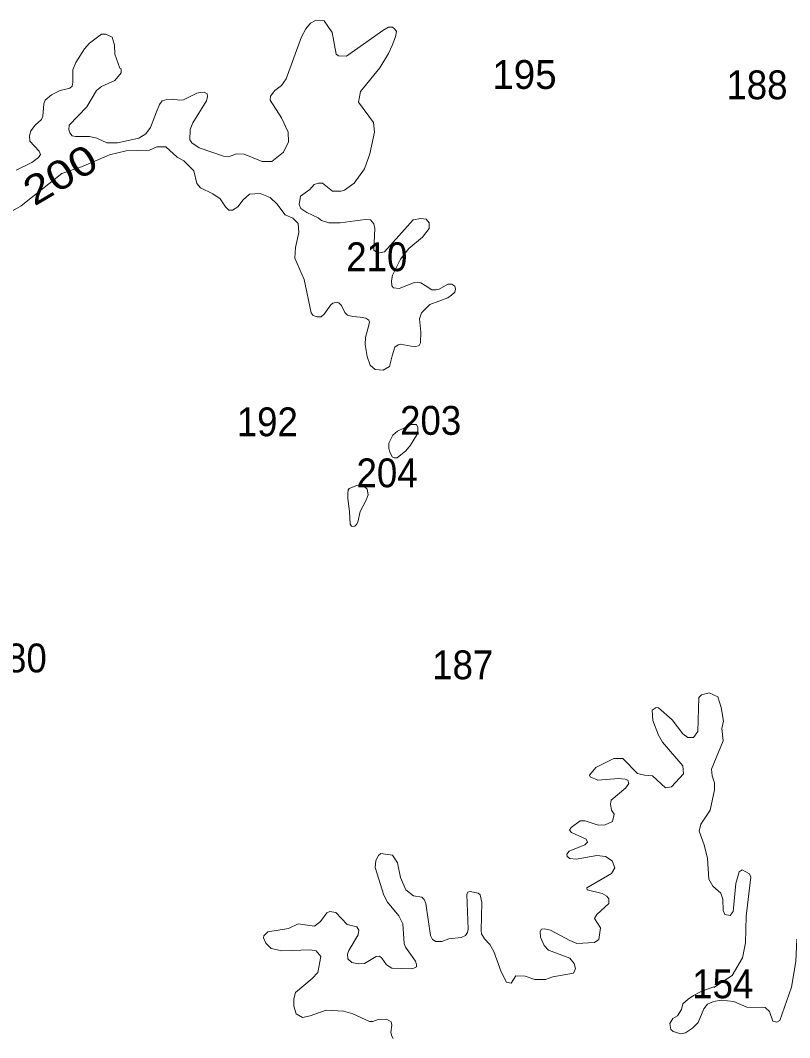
# Model space of a CAD drawing. Extents: x 499.9 to 555.3, y 9281.5 to 9336.8.
# Drawn here: x 524.08 to 528.35, y 9331.07 to 9336.71 of the extents above; entities that cross this region are included whole.
import ezdxf
from ezdxf.enums import TextEntityAlignment as Align

# ---------------------------------------------------------------- set-up
doc = ezdxf.new("R2010")
doc.units = 0
doc.header["$LTSCALE"] = 0.064
doc.layers.add('2', color=7, linetype='Continuous', lineweight=13)
doc.layers.add('21', color=7, linetype='Continuous')
doc.layers.add('61', color=7, linetype='Continuous')

msp = doc.modelspace()

# ---------------------------------------------------------------- linework, layer by layer
at = {"layer": '2'}
for points in [[(526.3906, 9335.2186), (526.3669, 9335.2186), (526.3294, 9335.2442), (526.3049, 9335.2586), (526.2873, 9335.2624), (526.27, 9335.2592), (526.1864, 9335.2264), (526.1547, 9335.2296), (526.1451, 9335.241), (526.1438, 9335.2693), (526.1491, 9335.3005), (526.1933, 9335.3903), (526.24, 9335.4481), (526.3154, 9335.5111), (526.3523, 9335.5599), (526.3525, 9335.5912), (526.3349, 9335.6121), (526.3054, 9335.6147), (526.2634, 9335.6082), (526.1047, 9335.4307), (526.068, 9335.4223), (526.0453, 9335.439), (526.0514, 9335.559), (526.0449, 9335.5863), (526.0275, 9335.608), (525.9979, 9335.6095), (525.8583, 9335.5908), (525.7946, 9335.5911), (525.7551, 9335.6033), (525.7364, 9335.6195), (525.673, 9335.649), (525.6407, 9335.6709), (525.6302, 9335.6928), (525.6387, 9335.7383), (525.6898, 9335.7753), (525.7133, 9335.8042), (525.7387, 9335.812), (525.7602, 9335.8102), (525.8153, 9335.7661), (525.8614, 9335.766), (525.883, 9335.7719), (525.9354, 9335.8106), (525.993, 9335.8909), (526.0234, 9335.9746), (526.0483, 9336.0946), (526.0432, 9336.1486), (525.9606, 9336.2609), (525.9714, 9336.3194), (526.0775, 9336.451), (526.1263, 9336.5299), (526.1466, 9336.5745), (526.1644, 9336.6222), (526.1703, 9336.6522), (526.1622, 9336.6661), (526.1487, 9336.6764), (526.1257, 9336.6774), (526.0944, 9336.659), (525.8926, 9336.5166), (525.8495, 9336.5174), (525.8368, 9336.5274), (525.8148, 9336.6463), (525.7704, 9336.7118), (525.7212, 9336.7145), (525.6945, 9336.6993), (525.6673, 9336.6671), (525.6442, 9336.6229), (525.5581, 9336.3899), (525.5331, 9336.3524), (525.4967, 9336.325), (525.4719, 9336.2934), (525.4693, 9336.2721), (525.5327, 9336.1734), (525.5692, 9336.0945), (525.5722, 9336.0406), (525.5438, 9335.9826), (525.4801, 9335.9317), (525.4262, 9335.9316), (525.3257, 9335.9714), (525.2831, 9335.9739), (525.2398, 9335.9572), (525.2104, 9335.9601), (525.0767, 9336.0076), (525.0356, 9336.0341), (525.0251, 9336.0522), (525.0257, 9336.1082), (525.0403, 9336.1463), (525.1169, 9336.2684), (525.1231, 9336.2927), (525.1206, 9336.3073), (525.1038, 9336.3154), (525.0813, 9336.3146), (525.0626, 9336.3099), (524.9886, 9336.274), (524.9685, 9336.2723), (524.9287, 9336.2767)], [(524.8065, 9336.1198), (524.7808, 9336.0855), (524.7424, 9336.0609), (524.6239, 9336.035), (524.5634, 9336.035), (524.5093, 9336.0603), (524.4682, 9336.0692), (524.3909, 9336.0693), (524.3721, 9336.0738), (524.3582, 9336.0899), (524.3528, 9336.1066), (524.3556, 9336.133), (524.4536, 9336.2339), (524.5075, 9336.3251), (524.5344, 9336.3474), (524.6079, 9336.3805), (524.6429, 9336.4224), (524.6428, 9336.4446), (524.636, 9336.4492), (524.6078, 9336.5273), (524.6062, 9336.5776), (524.5928, 9336.6203), (524.5578, 9336.6377), (524.5343, 9336.6376), (524.4674, 9336.5878), (524.4405, 9336.5563), (524.3925, 9336.4806), (524.3759, 9336.4408), (524.3763, 9336.3717), (524.3713, 9336.3491), (524.3591, 9336.339), (524.3058, 9336.3261), (524.2579, 9336.302), (524.2227, 9336.2712), (524.215, 9336.2517), (524.2093, 9336.1828), (524.2023, 9336.1647), (524.1672, 9336.1336), (524.1422, 9336.1013), (524.1347, 9336.0734), (524.1372, 9336.0447), (524.1887, 9335.9893), (524.1953, 9335.9696), (524.1842, 9335.9542), (524.1476, 9335.9257), (524.0605, 9335.8838)], [(524.9287, 9336.2767), (524.8968, 9336.2754), (524.8714, 9336.2673), (524.8566, 9336.2467), (524.8396, 9336.2069), (524.8065, 9336.1198)], [(524.0027, 9335.6357), (524.0886, 9335.6862), (524.3153, 9335.8639), (524.4235, 9335.9015), (524.5789, 9335.9688), (524.6717, 9335.9903), (524.8004, 9335.9934), (524.8421, 9336.0124), (524.8912, 9336.0123), (524.9541, 9335.955), (524.9906, 9335.9341), (525.0471, 9335.8788), (525.0638, 9335.81), (525.0835, 9335.7857), (525.1516, 9335.752), (525.193, 9335.7234), (525.2217, 9335.6795), (525.241, 9335.6616), (525.2612, 9335.6615), (525.2909, 9335.6806), (525.3195, 9335.7182), (525.3546, 9335.7497), (525.4149, 9335.7531), (525.4706, 9335.7308), (525.5072, 9335.6959), (525.5536, 9335.6356), (525.5953, 9335.6173), (525.6252, 9335.5874), (525.6297, 9335.5368), (525.6107, 9335.4533), (525.6076, 9335.395), (525.6578, 9335.2772), (525.6969, 9335.0915), (525.7086, 9335.076), (525.7313, 9335.0698), (525.7539, 9335.0692), (525.7703, 9335.0844), (525.8068, 9335.1361), (525.818, 9335.146), (525.84, 9335.151), (525.8514, 9335.1473), (525.8652, 9335.1324), (525.8841, 9335.0938), (525.8995, 9335.0784), (525.9287, 9335.0705), (525.9689, 9335.0684), (526.001, 9335.0617), (526.0173, 9335.0515), (526.0205, 9335.0404), (526.0179, 9335.0236), (525.9991, 9334.9542), (525.9962, 9334.9168), (526.0085, 9334.85), (526.0246, 9334.8013), (526.0517, 9334.7774), (526.0961, 9334.7731), (526.1318, 9334.7941), (526.1461, 9334.8532), (526.161, 9334.9003), (526.1799, 9334.9149), (526.1913, 9334.9172), (526.2733, 9334.9022), (526.2973, 9334.9113), (526.3039, 9334.9246), (526.3065, 9334.9843), (526.2984, 9335.0585), (526.3096, 9335.0912), (526.3566, 9335.1383), (526.4564, 9335.1744), (526.476, 9335.1895), (526.4936, 9335.2064), (526.4984, 9335.2221)], [(526.4984, 9335.2221), (526.4937, 9335.2403), (526.4779, 9335.2505), (526.4549, 9335.2499), (526.4074, 9335.2222), (526.3906, 9335.2186)], [(527.2166, 9332.2738), (527.29, 9332.2487), (527.328, 9332.2508), (527.3698, 9332.2687), (527.3773, 9332.3092), (527.3641, 9332.3314), (527.3584, 9332.3657), (527.3615, 9332.3877), (527.4422, 9332.4555), (527.4597, 9332.481), (527.4535, 9332.4982), (527.4392, 9332.505), (527.4021, 9332.5079), (527.2867, 9332.4989), (527.2445, 9332.5173), (527.2409, 9332.5272), (527.2756, 9332.5685), (527.3755, 9332.6194), (527.4265, 9332.6194), (527.5081, 9332.5354), (527.5462, 9332.5256), (527.5911, 9332.5234), (527.6633, 9332.4563), (527.6962, 9332.4625), (527.7629, 9332.5331), (527.7593, 9332.5788), (527.6464, 9332.7102), (527.6244, 9332.7477), (527.5923, 9332.8306), (527.5882, 9332.8877), (527.6107, 9332.9018), (527.6239, 9332.9), (527.7004, 9332.8343), (527.7592, 9332.7554), (527.7875, 9332.7362), (527.8174, 9332.7359), (527.8421, 9332.7689), (527.8475, 9332.9579), (527.8625, 9332.9721), (527.905, 9332.9836), (527.9528, 9332.9603), (527.9723, 9332.9019), (527.9851, 9332.8255), (527.9759, 9332.7858), (527.982, 9332.7165), (527.9187, 9332.5605), (527.9216, 9332.5231), (527.9344, 9332.4833), (527.9343, 9332.4452), (527.9104, 9332.3315), (527.8582, 9332.255), (527.8488, 9332.2161), (527.8773, 9332.1397), (527.8962, 9332.064), (527.903, 9331.9488), (527.925, 9331.9097), (527.9695, 9331.8722), (527.9803, 9331.838), (527.9832, 9331.7754), (527.9921, 9331.7524), (528.0218, 9331.7474), (528.0374, 9331.7706), (528.0539, 9331.9247), (528.0717, 9331.9895), (528.0879, 9332.0014), (528.1289, 9331.9784), (528.1364, 9331.9597), (528.1098, 9331.7445), (528.1067, 9331.5967), (528.0897, 9331.5124), (528.0319, 9331.4148), (527.9317, 9331.3488)], [(527.2232, 9332.1712), (527.1412, 9332.2091), (527.1298, 9332.2221), (527.14, 9332.2369), (527.1903, 9332.2739), (527.2166, 9332.2738)], [(525.9602, 9331.48), (525.9942, 9331.4817), (526.0573, 9331.5207), (526.0762, 9331.5212), (526.0893, 9331.511), (526.1154, 9331.4737), (526.1456, 9331.4547), (526.2524, 9331.4527), (526.2677, 9331.4551), (526.2814, 9331.4623), (526.2813, 9331.4768), (526.2766, 9331.4938), (526.2213, 9331.5723), (526.2126, 9331.5931), (526.2057, 9331.7024), (526.1836, 9331.7457), (526.1203, 9331.8226), (526.1008, 9331.8604), (526.0521, 9332.015), (526.0563, 9332.0537), (526.0709, 9332.0813), (526.0842, 9332.0925), (526.1489, 9332.0824), (526.1762, 9332.04), (526.1934, 9331.959), (526.222, 9331.891), (526.2655, 9331.8561), (526.3106, 9331.8487), (526.3234, 9331.8368), (526.3339, 9331.8145), (526.3588, 9331.6373), (526.3702, 9331.615), (526.3893, 9331.6034), (526.4224, 9331.6042), (526.4607, 9331.6182), (526.529, 9331.626), (526.5544, 9331.637), (526.5648, 9331.653), (526.5691, 9331.6727), (526.5609, 9331.8643), (526.5658, 9331.8767), (526.5801, 9331.8808), (526.6236, 9331.8714), (526.6353, 9331.8618), (526.6435, 9331.8203), (526.6396, 9331.6644), (526.6424, 9331.6452), (526.6593, 9331.6191), (526.6877, 9331.5871), (526.7105, 9331.5483), (526.751, 9331.4352), (526.7808, 9331.3783), (526.8077, 9331.3726), (526.8335, 9331.413), (526.884, 9331.4113), (526.9382, 9331.3925), (526.9969, 9331.3924), (527.0385, 9331.407), (527.1526, 9331.4276), (527.1638, 9331.4529), (527.1572, 9331.4808), (527.1314, 9331.5119), (527.0146, 9331.5563), (526.9896, 9331.5812), (526.9705, 9331.6281), (526.9672, 9331.6587), (526.9755, 9331.6721), (526.9919, 9331.6744), (527.0253, 9331.6671), (527.1321, 9331.6082), (527.1712, 9331.5929), (527.2691, 9331.5979), (527.2931, 9331.6142), (527.3026, 9331.679), (527.2698, 9331.7304), (527.282, 9331.7535), (527.3481, 9331.814), (527.3486, 9331.8403), (527.3373, 9331.8554), (527.3119, 9331.8706), (527.2281, 9331.8901), (527.2275, 9331.9012), (527.363, 9331.9807), (527.3822, 9332.0125), (527.3677, 9332.051), (527.3305, 9332.076), (527.2819, 9332.0814), (527.1681, 9332.061), (527.133, 9332.064), (527.1167, 9332.0753), (527.1151, 9332.0878), (527.1281, 9332.1039), (527.2158, 9332.1401), (527.2304, 9332.1554), (527.2232, 9332.1712)], [(526.1532, 9331.0645), (526.1445, 9331.0775), (526.1399, 9331.0977), (526.1455, 9331.1386), (526.1415, 9331.157), (526.1149, 9331.1726), (526.0699, 9331.1711), (526.0404, 9331.1601), (526.0213, 9331.1602), (525.9292, 9331.2016), (525.8763, 9331.2173), (525.7812, 9331.2218), (525.6925, 9331.1905), (525.6496, 9331.1818), (525.6143, 9331.203), (525.6007, 9331.2438), (525.6008, 9331.2851), (525.6108, 9331.321), (525.7035, 9331.3982), (525.7346, 9331.4324), (525.7518, 9331.5202), (525.7258, 9331.551), (525.6923, 9331.557), (525.5344, 9331.5516), (525.4753, 9331.5653), (525.4465, 9331.5936), (525.433, 9331.6234), (525.4347, 9331.6348), (525.4568, 9331.6569), (525.5718, 9331.6756), (525.625, 9331.7011), (525.7156, 9331.6887), (525.7497, 9331.7145), (525.784, 9331.7623), (525.8002, 9331.7708), (525.8352, 9331.7638), (525.8967, 9331.697), (525.9506, 9331.6849), (525.9621, 9331.6661), (525.9588, 9331.6396)], [(525.9588, 9331.6396), (525.9066, 9331.5539), (525.8983, 9331.5324), (525.9004, 9331.5081), (525.9223, 9331.4869), (525.9602, 9331.48)], [(527.7299, 9331.1907), (527.7034, 9331.1757), (527.6862, 9331.1484), (527.6923, 9331.1145), (527.7063, 9331.1041), (527.7473, 9331.091), (527.7744, 9331.0964), (527.8125, 9331.1229), (527.8444, 9331.1548), (527.8749, 9331.2297), (527.8958, 9331.2554), (527.9287, 9331.2708), (527.9715, 9331.2785), (528.0414, 9331.2707), (528.1142, 9331.2398), (528.2155, 9331.2375), (528.2395, 9331.2146), (528.259, 9331.1609), (528.2797, 9331.1556), (528.2969, 9331.1649), (528.3625, 9331.3509), (528.3866, 9331.4927), (528.392, 9331.6169)], [(527.9307, 9331.3525), (527.8856, 9331.3361), (527.8529, 9331.3218), (527.818, 9331.3033), (527.7894, 9331.2829), (527.7586, 9331.2583), (527.7525, 9331.2255), (527.7299, 9331.1907)]]:
    msp.add_lwpolyline(points, dxfattribs=at)
for points in [[(526.2489, 9334.3581), (526.2843, 9334.4154), (526.2899, 9334.439), (526.289, 9334.4551), (526.2812, 9334.4712), (526.2546, 9334.4714), (526.1771, 9334.4359), (526.1499, 9334.412), (526.1287, 9334.3693), (526.1282, 9334.3382), (526.1341, 9334.3196), (526.147, 9334.2933), (526.1588, 9334.2871), (526.174, 9334.288), (526.2221, 9334.3258)], [(526.0021, 9334.0527), (526.0141, 9334.0823), (526.0074, 9334.1136), (525.9903, 9334.1303), (525.9501, 9334.1335), (525.9081, 9334.1162), (525.9019, 9334.1073), (525.9005, 9334.0916), (525.9005, 9334.0623), (525.9105, 9333.9902), (525.9147, 9333.9193), (525.921, 9333.9084), (525.9298, 9333.9041), (525.9398, 9333.9077), (525.9482, 9333.9164), (525.9564, 9333.93), (525.9702, 9333.9902)]]:
    msp.add_lwpolyline(points, close=True, dxfattribs=at)

# ---------------------------------------------------------------- texts
at = {"layer": '21'}
msp.add_text('195', height=0.16, dxfattribs=at).set_placement((526.7021, 9336.334))
at = {"layer": '21', "width": 0.95}
for s, p in [('188', (528.0007, 9336.2766)), ('210', (525.8919, 9335.3227)), ('192', (525.2846, 9334.4068)), ('203', (526.1907, 9334.4148)), ('204', (525.9491, 9334.1238)), ('180', (523.8919, 9333.0967)), ('187', (526.3688, 9333.0586)), ('154', (527.8111, 9331.2888))]:
    msp.add_text(s, height=0.16, dxfattribs=at).set_placement(p)
at = {"layer": '61', "width": 1.2}
msp.add_text('200', height=0.16, rotation=30.466, dxfattribs=at).set_placement((524.3462, 9335.7893), align=Align.CENTER)

doc.saveas('drawing.dxf')
